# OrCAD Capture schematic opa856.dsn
size A
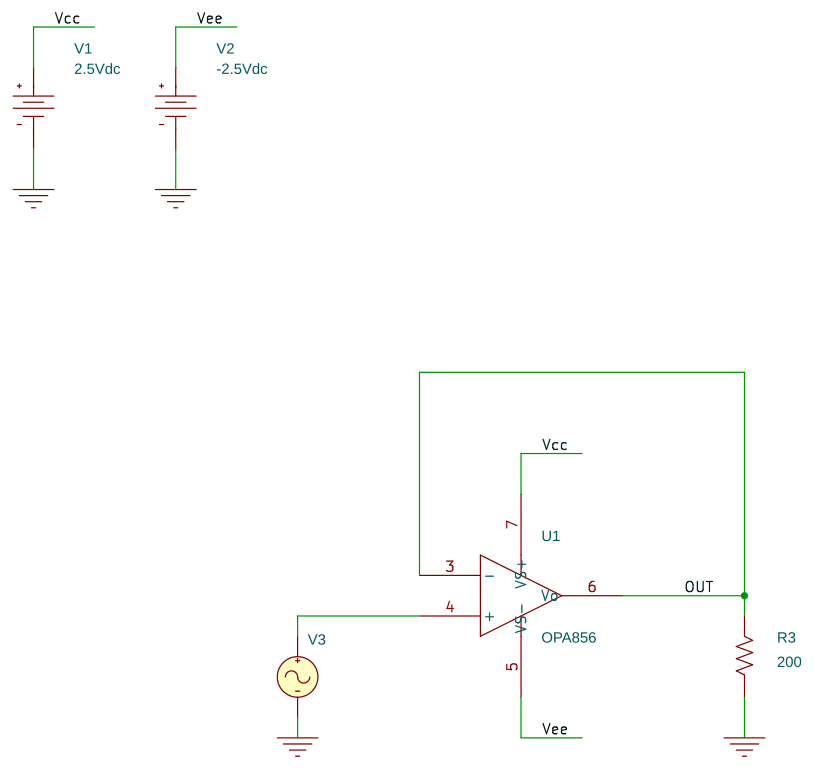
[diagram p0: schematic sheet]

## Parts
R3  200  [AX/RC05]
U1  OPA856
V1  VDC
V2  VDC
V3  VAC

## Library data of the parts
R3 = R
U1 = OPA856
V1 = VDC: DC: 2.5Vdc
V2 = VDC: DC: -2.5Vdc
V3 = VAC

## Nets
Vcc: U1.7(VS+) V1.0(+)
Vee: U1.5(VS-) V2.0(+)
0: R3.1 V1.1(-) V2.1(-) V3.2(-)
OUT: R3.2 U1.3(-) U1.6(Vo)
N03033: U1.4(+) V3.1(+)
